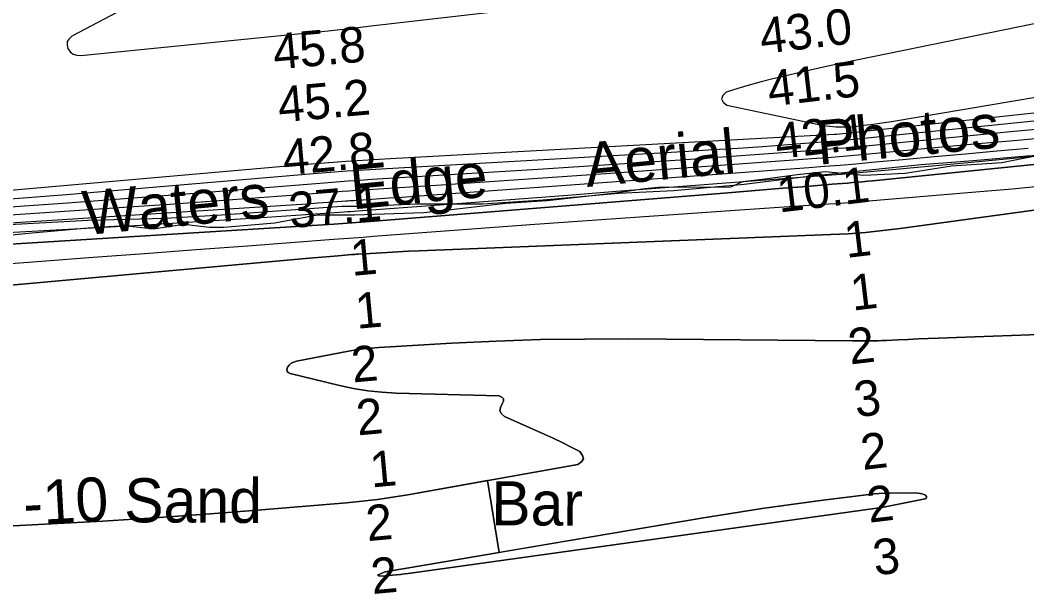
# Model space of a CAD drawing. Extents: x 3192986 to 3230865, y 867483 to 892886.
# Drawn here: x 3199829 to 3201724, y 879588 to 880658 of the extents above; entities that cross this region are included whole.
import ezdxf

# ---------------------------------------------------------------- set-up
doc = ezdxf.new("R2010")
doc.units = 0
for name, color, linetype in [('V-RIVR-EDGE', 7, 'Continuous'), ('V-RIVR-IDEN', 7, 'Continuous'), ('V-RIVR-RANG', 7, 'Continuous'), ('V-SITE-VEGE', 7, 'Continuous'), ('V-TOPO-DPTH', 7, 'Continuous'), ('V-TOPO-MAJR', 7, 'Continuous'), ('V-TOPO-MINR', 7, 'Continuous'), ('V-TOPO-MINR-IDEN', 7, 'Continuous'), ('V-TOPO-WATR', 7, 'Continuous')]:
    doc.layers.add(name, color=color, linetype=linetype)

msp = doc.modelspace()

# ---------------------------------------------------------------- linework, layer by layer
at = {"layer": 'V-RIVR-EDGE'}
msp.add_lwpolyline([(3201772.1, 880408.8), (3201677.3, 880389.9), (3201582.1, 880383.6), (3201495.2, 880369.9), (3201416.9, 880365.7), (3201344.3, 880372.9), (3201291.7, 880366.9), (3201231.7, 880359.2), (3201188.7, 880354.1), (3201166, 880344.2), (3201107.4, 880343.5), (3201036.1, 880344.1), (3201004.8, 880340.7), (3200949.5, 880332.6), (3200820.8, 880318.1), (3200743, 880313.1), (3200640.4, 880301.6), (3200588.7, 880295.6), (3200458.2, 880291.2), (3200388.3, 880291.3), (3200308.2, 880276.3), (3200212.2, 880268.3), (3200184.3, 880267.9), (3200136.5, 880273.7), (3200080, 880264.7), (3200024.8, 880271.4), (3199956.6, 880266.8), (3199851.4, 880257.5), (3199780.5, 880250.7)], dxfattribs=at)
at = {"layer": 'V-SITE-VEGE'}
for p, q in [((3201723.6, 880402.5), (3201623.1, 880393.5)), ((3201828.9, 880407.5), (3201723.6, 880402.5)), ((3201524.9, 880386.1), (3201421.9, 880375.6)), ((3201623.1, 880393.5), (3201524.9, 880386.1)), ((3201302.7, 880362.8), (3201192, 880349.2)), ((3201421.9, 880375.6), (3201302.7, 880362.8)), ((3201192, 880349.2), (3201059.4, 880337.2)), ((3200813.1, 880319.5), (3200699.3, 880312.1)), ((3200955, 880332.2), (3200813.1, 880319.5)), ((3201059.4, 880337.2), (3200955, 880332.2)), ((3200434.3, 880307.7), (3200207.5, 880291.4)), ((3200473.3, 880307.5), (3200434.3, 880307.7)), ((3200577, 880311.8), (3200473.3, 880307.5)), ((3200699.3, 880312.1), (3200577, 880311.8)), ((3199955.8, 880281.4), (3199784.3, 880271.9)), ((3200102.3, 880284.8), (3199955.8, 880281.4)), ((3200207.5, 880291.4), (3200102.3, 880284.8))]:
    msp.add_line(p, q, dxfattribs=at)
at = {"layer": 'V-TOPO-DPTH'}
for points in [[(3201726.7, 880416.8), (3201667.7, 880411.5), (3201608.7, 880406.2), (3201549.7, 880400.8), (3201490.6, 880395.5), (3201431.5, 880390.1), (3201402, 880387.5), (3201372.6, 880385), (3201343.1, 880382.7), (3201313.6, 880380.4), (3200597.2, 880328.3), (3200572.6, 880326.5), (3200548, 880324.8), (3200523.4, 880323.1), (3200498.8, 880321.4), (3200457.1, 880318.5), (3200453.3, 880318.3), (3200449.6, 880318), (3200445.8, 880317.8), (3200442, 880317.5), (3200409.3, 880315.1), (3200389.2, 880313.6), (3200369.1, 880312.2), (3200349, 880310.9), (3200328.9, 880309.6), (3199731.1, 880271)], [(3199739.3, 880232.2), (3200419.2, 880274.3), (3200436.3, 880275.4), (3200453.4, 880276.6), (3200470.4, 880277.9), (3200487.5, 880279.2), (3201153.4, 880332.8), (3201190.6, 880335.8), (3201227.8, 880338.8), (3201265, 880341.8), (3201302.2, 880344.8), (3201357.5, 880349.3), (3201367, 880350.1), (3201376.6, 880350.9), (3201386.2, 880351.7), (3201395.8, 880352.6), (3201405.4, 880353.4), (3201415, 880354.3), (3201424.5, 880355.2), (3201434.1, 880356.2), (3201898.6, 880403.1)], [(3199739.3, 880232.2), (3200419.2, 880274.3), (3200436.3, 880275.4), (3200453.4, 880276.6), (3200470.4, 880277.9), (3200487.5, 880279.2), (3201153.4, 880332.8), (3201190.6, 880335.8), (3201227.8, 880338.8), (3201265, 880341.8), (3201302.2, 880344.8), (3201357.5, 880349.3), (3201367, 880350.1), (3201376.6, 880350.9), (3201386.2, 880351.7), (3201395.8, 880352.6), (3201405.4, 880353.4), (3201415, 880354.3), (3201424.5, 880355.2), (3201434.1, 880356.2), (3201898.6, 880403.1)], [(3199754.9, 880154.5), (3200365.6, 880209.4), (3200381.1, 880210.8), (3200396.7, 880212.1), (3200412.2, 880213.5), (3200427.7, 880214.8), (3200452.3, 880216.9), (3200455.6, 880217.2), (3200458.8, 880217.4), (3200462.1, 880217.7), (3200465.3, 880217.9), (3200499.2, 880220), (3200519.4, 880221.2), (3200539.6, 880222.4), (3200559.8, 880223.3), (3200580, 880224.2), (3201355.3, 880254.6), (3201371.7, 880255.3), (3201388, 880256.3), (3201404.2, 880257.5), (3201420.5, 880258.9), (3201436.8, 880260.5), (3201453, 880262.3), (3201469.2, 880264.3), (3201485.4, 880266.4), (3202021.9, 880339.3)], [(3202021.9, 880339.3), (3201485.4, 880266.4), (3201469.2, 880264.3), (3201453, 880262.3), (3201436.8, 880260.5), (3201420.5, 880258.9), (3201404.2, 880257.5), (3201388, 880256.3), (3201371.7, 880255.3), (3201355.3, 880254.6), (3200580, 880224.2), (3200559.8, 880223.3), (3200539.6, 880222.4), (3200519.4, 880221.2), (3200499.2, 880220), (3200465.3, 880217.9), (3200462.1, 880217.7), (3200458.8, 880217.4), (3200455.6, 880217.2), (3200452.3, 880216.9), (3200427.7, 880214.8), (3200412.2, 880213.5), (3200396.7, 880212.1), (3200381.1, 880210.8), (3200365.6, 880209.4), (3199754.9, 880154.5)], [(3201798.7, 880068.6), (3201557.2, 880059.7), (3201538.3, 880058.9), (3201519.4, 880058.2), (3201500.6, 880057.3), (3201481.7, 880056.4), (3201459.9, 880055.4), (3201451.9, 880055), (3201443.9, 880054.8), (3201436, 880054.6), (3201428, 880054.5), (3201420, 880054.5), (3201412, 880054.5), (3201404.1, 880054.6), (3201396.1, 880054.6), (3200974.9, 880058.2), (3200891.5, 880058.1), (3200808.2, 880056.9), (3200724.9, 880054.1), (3200641.6, 880050.1), (3200503.9, 880042.2), (3200489.5, 880041.1), (3200475.2, 880039.6), (3200461, 880037.5), (3200446.8, 880035.1), (3200348.8, 880016.4), (3200343.7, 880014.8), (3200339.1, 880012.4), (3200335.3, 880009), (3200331.9, 880004.9), (3200330.9, 880001), (3200331.2, 879997.6), (3200333.4, 879995), (3200336.8, 879992.9), (3200430, 879970.5), (3200456.5, 879965.1), (3200483.1, 879960.7), (3200509.8, 879958), (3200536.8, 879956.4), (3200730.5, 879951.2), (3200735.6, 879948.7), (3200738.6, 879945.5), (3200738.5, 879941), (3200736.4, 879935.8), (3200733, 879929.1), (3200732.1, 879922.9), (3200735.1, 879917.3), (3200740.5, 879912.2), (3200815.4, 879879), (3200832.4, 879871.2), (3200849.2, 879863.1), (3200865.9, 879854.7), (3200882.5, 879846), (3200887.6, 879839), (3200889.2, 879832.5), (3200885.6, 879826.8), (3200878.6, 879821.7), (3200558.8, 879764.8), (3200530.1, 879760.1), (3200501.2, 879755.9), (3200472.3, 879752.6), (3200443.3, 879749.8), (3200275.7, 879736), (3200178.5, 879728.4), (3200081.3, 879721.5), (3199984, 879715.4), (3199886.7, 879709.9), (3199718.6, 879701.1)], [(3201798.7, 880068.6), (3201557.2, 880059.7), (3201538.3, 880058.9), (3201519.4, 880058.2), (3201500.6, 880057.3), (3201481.7, 880056.4), (3201459.9, 880055.4), (3201451.9, 880055), (3201443.9, 880054.8), (3201436, 880054.6), (3201428, 880054.5), (3201420, 880054.5), (3201412, 880054.5), (3201404.1, 880054.6), (3201396.1, 880054.6), (3200974.9, 880058.2), (3200891.5, 880058.1), (3200808.2, 880056.9), (3200724.9, 880054.1), (3200641.6, 880050.1), (3200503.9, 880042.2), (3200489.5, 880041.1), (3200475.2, 880039.6), (3200461, 880037.5), (3200446.8, 880035.1), (3200348.8, 880016.4), (3200343.7, 880014.8), (3200339.1, 880012.4), (3200335.3, 880009), (3200331.9, 880004.9), (3200330.9, 880001), (3200331.2, 879997.6), (3200333.4, 879995), (3200336.8, 879992.9), (3200430, 879970.5), (3200456.5, 879965.1), (3200483.1, 879960.7), (3200509.8, 879958), (3200536.8, 879956.4), (3200730.5, 879951.2), (3200735.6, 879948.7), (3200738.6, 879945.5), (3200738.5, 879941), (3200736.4, 879935.8), (3200733, 879929.1), (3200732.1, 879922.9), (3200735.1, 879917.3), (3200740.5, 879912.2), (3200815.4, 879879), (3200832.4, 879871.2), (3200849.2, 879863.1), (3200865.9, 879854.7), (3200882.5, 879846), (3200887.6, 879839), (3200889.2, 879832.5), (3200885.6, 879826.8), (3200878.6, 879821.7), (3200714.8, 879792.6), (3200708.6, 879791.5), (3200730.7, 879656), (3200736.9, 879657.1)], [(3200730.7, 879656), (3200708.6, 879791.5), (3200558.8, 879764.8), (3200530.1, 879760.1), (3200501.2, 879755.9), (3200472.3, 879752.6), (3200443.3, 879749.8), (3200275.7, 879736), (3200178.5, 879728.4), (3200081.3, 879721.5), (3199984, 879715.4), (3199886.7, 879709.9), (3199718.6, 879701.1)], [(3201449.5, 879740.7), (3201453.4, 879741.4), (3201457.2, 879742.1), (3201532.6, 879757), (3201534.5, 879758.5), (3201535.5, 879760.1), (3201535, 879761.9), (3201533.5, 879763.8), (3201528.7, 879765.8), (3201523.8, 879767.3), (3201518.7, 879768.1), (3201513.5, 879768.5), (3201465.9, 879768.1), (3201456.1, 879767.8), (3201446.3, 879767.3), (3201436.5, 879766.5), (3201426.8, 879765.5), (3201335.8, 879754), (3201280.6, 879746.7), (3201225.5, 879738.9), (3201170.5, 879730.4), (3201115.6, 879721.4), (3200519.5, 879620.2), (3200516.7, 879619.6), (3200513.9, 879618.9), (3200511.3, 879617.9), (3200508.6, 879616.9), (3200502.7, 879614.3), (3200502.4, 879614), (3200502.3, 879613.7), (3200502.4, 879613.3), (3200502.6, 879613), (3200503.9, 879612.5), (3200504.6, 879612.4), (3200505.3, 879612.3), (3200512.9, 879611.9), (3200515.3, 879611.9), (3200516.2, 879612), (3200529.5, 879613.2), (3200537, 879614), (3200544.5, 879614.8), (3200552, 879615.7), (3200559.4, 879616.7), (3201441.7, 879739.5), (3201445.6, 879740.1), (3201449.5, 879740.7)], [(3200736.9, 879657.1), (3201115.6, 879721.4), (3201170.5, 879730.4), (3201225.5, 879738.9), (3201280.6, 879746.7), (3201335.8, 879754), (3201426.8, 879765.5), (3201436.5, 879766.5), (3201446.3, 879767.3), (3201456.1, 879767.8), (3201465.9, 879768.1), (3201513.5, 879768.5), (3201518.7, 879768.1), (3201523.8, 879767.3), (3201528.7, 879765.8), (3201533.5, 879763.8), (3201535, 879761.9), (3201535.5, 879760.1), (3201534.5, 879758.5), (3201532.6, 879757), (3201457.2, 879742.1), (3201453.4, 879741.4), (3201449.5, 879740.7)], [(3201449.5, 879740.7), (3201445.6, 879740.1), (3201441.7, 879739.5), (3200559.4, 879616.7), (3200552, 879615.7), (3200544.5, 879614.8), (3200537, 879614), (3200529.5, 879613.2), (3200516.2, 879612), (3200515.3, 879611.9), (3200512.9, 879611.9), (3200505.3, 879612.3), (3200504.6, 879612.4), (3200503.9, 879612.5), (3200502.6, 879613), (3200502.4, 879613.3), (3200502.3, 879613.7), (3200502.4, 879614), (3200502.7, 879614.3), (3200508.6, 879616.9), (3200511.3, 879617.9), (3200513.9, 879618.9), (3200516.7, 879619.6), (3200519.5, 879620.2), (3200730.7, 879656)]]:
    msp.add_lwpolyline(points, dxfattribs=at)
at = {"layer": 'V-TOPO-MAJR'}
msp.add_lwpolyline([(3201842.4, 880479), (3201380, 880431.9), (3201373.6, 880431.3), (3201367.1, 880430.7), (3201360.6, 880430.2), (3201354.2, 880429.7), (3201273.8, 880423.6), (3201227.1, 880420.2), (3201180.4, 880417), (3201133.7, 880414), (3201087, 880411.2), (3200508.2, 880377.9), (3200476.3, 880375.9), (3200444.4, 880373.8), (3200412.5, 880371.4), (3200380.7, 880368.8), (3199915.9, 880329.7), (3199875.1, 880326.3), (3199834.3, 880323), (3199793.5, 880319.9)], dxfattribs=at)
at = {"layer": 'V-TOPO-MINR'}
for points in [[(3200347, 880850.1), (3199925.8, 880628.1), (3199920.6, 880623.4), (3199917.4, 880618.1), (3199916.9, 880611.9), (3199918.3, 880605.1), (3199923, 880599), (3199928.4, 880594.5), (3199935.1, 880592.3), (3199942.7, 880591.6), (3200350.6, 880632.5), (3200385.3, 880636), (3200420, 880639.7), (3200454.6, 880643.5), (3200489.3, 880647.4), (3201271.9, 880737.8)], [(3201738, 880651.5), (3201379, 880577.9), (3201364.6, 880574.9), (3201350.3, 880571.8), (3201335.9, 880568.6), (3201321.6, 880565.3), (3201245.8, 880547.7), (3201223.6, 880542.2), (3201201.6, 880536.2), (3201179.7, 880529.7), (3201158, 880522.7), (3201151.9, 880516.3), (3201149.4, 880510.1), (3201152.6, 880504.2), (3201159.4, 880498.5), (3201329.6, 880462.3), (3201347, 880459.4), (3201364.4, 880457.6), (3201381.8, 880457.5), (3201399.4, 880458.4), (3201416.9, 880460.4), (3201434.5, 880462.6), (3201452, 880465.1), (3201469.4, 880467.9), (3201974.5, 880552.9)], [(3201992.6, 880510.8), (3201365.8, 880443.4), (3201365.5, 880443.3), (3201361.8, 880443.1), (3200525.2, 880397.4), (3200484, 880395), (3200442.7, 880392.2), (3200401.5, 880389.1), (3200360.3, 880385.7), (3199681, 880326.2)], [(3201748.8, 880453.1), (3201693.1, 880447.9), (3201396.1, 880418.9), (3201382.5, 880417.7), (3201368.8, 880416.5), (3201355.2, 880415.3), (3201341.5, 880414.3), (3201177.3, 880402.3), (3201081.5, 880395.5), (3200985.7, 880388.9), (3200889.9, 880382.7), (3200794.1, 880376.7), (3200491.1, 880358.2), (3200468.6, 880356.8), (3200446.1, 880355.2), (3200423.6, 880353.6), (3200401.1, 880351.8), (3200164.8, 880332.8), (3200082.6, 880326.2), (3200000.4, 880319.9), (3199918.2, 880313.8), (3199836, 880307.9), (3199701.1, 880298.4)], [(3201787.3, 880439.1), (3201706.4, 880432), (3201625.5, 880424.7), (3201544.6, 880417.2), (3201413.4, 880404.9), (3201392, 880403), (3201370.6, 880401.1), (3201349.3, 880399.4), (3201327.9, 880397.8), (3200940.4, 880369.8), (3200858.3, 880363.9), (3200776.3, 880358.2), (3200694.2, 880352.7), (3200612.1, 880347.3), (3200474.1, 880338.4), (3200461, 880337.6), (3200447.8, 880336.7), (3200434.7, 880335.7), (3200421.6, 880334.7), (3200312.9, 880326.4), (3200245.4, 880321.2), (3200177.9, 880316.3), (3200110.4, 880311.5), (3200042.8, 880306.8), (3199716.1, 880284.8)], [(3201726.7, 880416.8), (3201667.7, 880411.5), (3201608.7, 880406.2), (3201549.7, 880400.8), (3201490.6, 880395.5), (3201431.5, 880390.1), (3201402, 880387.5), (3201372.6, 880385), (3201343.1, 880382.7), (3201313.6, 880380.4), (3200597.2, 880328.3), (3200572.6, 880326.5), (3200548, 880324.8), (3200523.4, 880323.1), (3200498.8, 880321.4), (3200457.1, 880318.5), (3200453.3, 880318.3), (3200449.6, 880318), (3200445.8, 880317.8), (3200442, 880317.5), (3200409.3, 880315.1), (3200389.2, 880313.6), (3200369.1, 880312.2), (3200349, 880310.9), (3200328.9, 880309.6), (3199731.1, 880271)], [(3202022, 880428.9), (3201580, 880386.7), (3201545.7, 880383.4), (3201511.5, 880380.3), (3201477.3, 880377.1), (3201443.1, 880374), (3201408.8, 880371), (3201374.6, 880368.1), (3201340.3, 880365.3), (3201306.1, 880362.6), (3200951.7, 880335.5), (3200868.3, 880329.1), (3200785, 880322.8), (3200701.6, 880316.5), (3200618.2, 880310.2), (3200464.2, 880298.7), (3200457.8, 880298.2), (3200451.4, 880297.8), (3200445, 880297.3), (3200438.6, 880296.9), (3200292.9, 880287), (3200213.6, 880281.7), (3200134.3, 880276.7), (3200055, 880271.9), (3199975.7, 880267.4), (3199748.4, 880254.8)], [(3201765.7, 880347.1), (3201696.8, 880340.4), (3201627.9, 880334.3), (3201411.6, 880316.3), (3201396.3, 880315.1), (3201381.1, 880313.9), (3201365.8, 880312.8), (3201350.5, 880311.7), (3201183.7, 880300.6), (3201085, 880293.9), (3200986.3, 880287.1), (3200887.6, 880280), (3200789, 880272.8), (3200493.1, 880250.8), (3200474.6, 880249.5), (3200456, 880248.1), (3200437.4, 880246.7), (3200418.8, 880245.3), (3200256.7, 880233.1), (3200159.8, 880225.9), (3200062.9, 880218.6), (3199965.9, 880211.4), (3199869, 880204.2), (3199711.4, 880192.4)], [(3202021.9, 880339.3), (3201485.4, 880266.4), (3201469.2, 880264.3), (3201453, 880262.3), (3201436.8, 880260.5), (3201420.5, 880258.9), (3201404.2, 880257.5), (3201388, 880256.3), (3201371.7, 880255.3), (3201355.3, 880254.6), (3200580, 880224.2), (3200559.8, 880223.3), (3200539.6, 880222.4), (3200519.4, 880221.2), (3200499.2, 880220), (3200465.3, 880217.9), (3200462.1, 880217.7), (3200458.8, 880217.4), (3200455.6, 880217.2), (3200452.3, 880216.9), (3200427.7, 880214.8), (3200412.2, 880213.5), (3200396.7, 880212.1), (3200381.1, 880210.8), (3200365.6, 880209.4), (3199754.9, 880154.5)], [(3199718.6, 879701.1), (3199886.7, 879709.9), (3199984, 879715.4), (3200081.3, 879721.5), (3200178.5, 879728.4), (3200275.7, 879736), (3200443.3, 879749.8), (3200472.3, 879752.6), (3200501.2, 879755.9), (3200530.1, 879760.1), (3200558.8, 879764.8), (3200878.6, 879821.7), (3200885.6, 879826.8), (3200889.2, 879832.5), (3200887.6, 879839), (3200882.5, 879846), (3200865.9, 879854.7), (3200849.2, 879863.1), (3200832.4, 879871.2), (3200815.4, 879879), (3200740.5, 879912.2), (3200735.1, 879917.3), (3200732.1, 879922.9), (3200733, 879929.1), (3200736.4, 879935.8), (3200738.5, 879941), (3200738.6, 879945.5), (3200735.6, 879948.7), (3200730.5, 879951.2), (3200536.8, 879956.4), (3200509.8, 879958), (3200483.1, 879960.7), (3200456.5, 879965.1), (3200430, 879970.5), (3200336.8, 879992.9), (3200333.4, 879995), (3200331.2, 879997.6), (3200330.9, 880001), (3200331.9, 880004.9), (3200335.3, 880009), (3200339.1, 880012.4), (3200343.7, 880014.8), (3200348.8, 880016.4), (3200446.8, 880035.1), (3200461, 880037.5), (3200475.2, 880039.6), (3200489.5, 880041.1), (3200503.9, 880042.2), (3200641.6, 880050.1), (3200724.9, 880054.1), (3200808.2, 880056.9), (3200891.5, 880058.1), (3200974.9, 880058.2), (3201396.1, 880054.6), (3201404.1, 880054.6), (3201412, 880054.5), (3201420, 880054.5), (3201428, 880054.5), (3201436, 880054.6), (3201443.9, 880054.8), (3201451.9, 880055), (3201459.9, 880055.4), (3201481.7, 880056.4), (3201500.6, 880057.3), (3201519.4, 880058.2), (3201538.3, 880058.9), (3201557.2, 880059.7), (3201798.7, 880068.6)], [(3201449.5, 879740.7), (3201453.4, 879741.4), (3201457.2, 879742.1), (3201532.6, 879757), (3201534.5, 879758.5), (3201535.5, 879760.1), (3201535, 879761.9), (3201533.5, 879763.8), (3201528.7, 879765.8), (3201523.8, 879767.3), (3201518.7, 879768.1), (3201513.5, 879768.5), (3201465.9, 879768.1), (3201456.1, 879767.8), (3201446.3, 879767.3), (3201436.5, 879766.5), (3201426.8, 879765.5), (3201335.8, 879754), (3201280.6, 879746.7), (3201225.5, 879738.9), (3201170.5, 879730.4), (3201115.6, 879721.4), (3200519.5, 879620.2), (3200516.7, 879619.6), (3200513.9, 879618.9), (3200511.3, 879617.9), (3200508.6, 879616.9), (3200502.7, 879614.3), (3200502.4, 879614), (3200502.3, 879613.7), (3200502.4, 879613.3), (3200502.6, 879613), (3200503.9, 879612.5), (3200504.6, 879612.4), (3200505.3, 879612.3), (3200512.9, 879611.9), (3200515.3, 879611.9), (3200516.2, 879612), (3200529.5, 879613.2), (3200537, 879614), (3200544.5, 879614.8), (3200552, 879615.7), (3200559.4, 879616.7), (3201441.7, 879739.5), (3201445.6, 879740.1), (3201449.5, 879740.7)]]:
    msp.add_lwpolyline(points, dxfattribs=at)
at = {"layer": 'V-TOPO-WATR'}
msp.add_lwpolyline([(3201898.6, 880403.1), (3201434.1, 880356.2), (3201424.5, 880355.2), (3201415, 880354.3), (3201405.4, 880353.4), (3201395.8, 880352.6), (3201386.2, 880351.7), (3201376.6, 880350.9), (3201367, 880350.1), (3201357.5, 880349.3), (3201302.2, 880344.8), (3201265, 880341.8), (3201227.8, 880338.8), (3201190.6, 880335.8), (3201153.4, 880332.8), (3200487.5, 880279.2), (3200470.4, 880277.9), (3200453.4, 880276.6), (3200436.3, 880275.4), (3200419.2, 880274.3), (3199739.3, 880232.2)], dxfattribs=at)

# ---------------------------------------------------------------- texts
at = {"layer": 'V-RIVR-IDEN'}
for s, rotation, p in [('Waters     Edge      Aerial     Photos             September      2012', 5.4766, (3199950.4, 880253.6)), ('Sand', 359.7093, (3200024.4, 879713.1)), ('Bar', 359.7093, (3200715.6, 879707.5))]:
    msp.add_text(s, height=83, rotation=rotation, dxfattribs=at).set_placement(p)
at = {"layer": 'V-RIVR-RANG'}
for s, rotation, p in [('43.0', 6.6683, (3201225, 880594.7)), ('45.8', 5.1183, (3200307.5, 880565.3)), ('41.5', 6.6683, (3201239.7, 880495.7)), ('45.2', 5.1183, (3200316.7, 880465.7)), ('42.1', 6.6683, (3201253.9, 880396.7)), ('42.8', 5.1183, (3200325.8, 880366.2)), ('10.1', 6.8543, (3201257.8, 880296.1)), ('37.1', 5.1183, (3200337.4, 880266.8)), ('1', 6.8543, (3201384.4, 880210.6)), ('1', 5.2795, (3200453.5, 880176.8)), ('1', 6.8543, (3201396.2, 880111.3)), ('1', 5.2795, (3200462.7, 880077.2)), ('2', 6.8543, (3201391.6, 880010)), ('2', 5.2795, (3200455.3, 879976.1)), ('3', 6.8543, (3201402.9, 879910.6)), ('2', 5.2795, (3200464.5, 879876.5)), ('2', 6.8543, (3201415.3, 879811.4)), ('1', 5.2795, (3200490.2, 879778.5)), ('2', 6.8543, (3201427.2, 879712.1)), ('2', 5.2795, (3200482.8, 879677.4)), ('3', 6.8543, (3201438.5, 879612.8)), ('2', 5.2795, (3200492, 879577.8))]:
    msp.add_text(s, height=67, rotation=rotation, dxfattribs=at).set_placement(p)
at = {"layer": 'V-TOPO-MINR-IDEN'}
msp.add_text('-10', height=83, rotation=3.2391, dxfattribs=at).set_placement((3199836.5, 879707))

doc.saveas('drawing.dxf')
